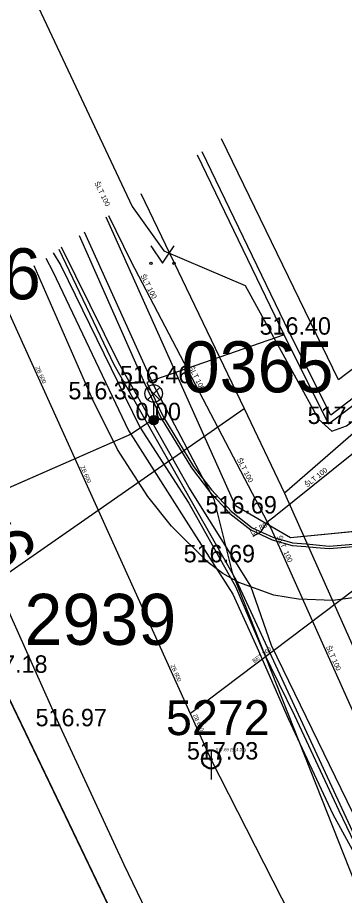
# Model space of a CAD drawing. Extents: x -668867 to -667827, y -1131943 to -1131019.
# Drawn here: x -668558.26 to -668544.21, y -1131122.93 to -1131085.18 of the extents above; entities that cross this region are included whole.
import ezdxf

# ---------------------------------------------------------------- set-up
doc = ezdxf.new("R2010")
doc.units = 0
for name, color, linetype in [('G_Bod_tecka', 7, 'Continuous'), ('G_Bod_vyska', 7, 'Continuous'), ('G_Bodove_pole', 7, 'Continuous'), ('G_Objekty_technicke', 7, 'Continuous'), ('G_Plochy_zpevnene', 7, 'Continuous'), ('G_Ploty', 7, 'Continuous'), ('G_Site-kanalizace', 7, 'Continuous'), ('G_Z_ELsilove_podz_kotovane', 7, 'Continuous'), ('G_Z_KANAL_podz_kotovane', 7, 'Continuous'), ('G_Z_KANAL_podz_priblizne', 7, 'Continuous'), ('G_Z_PLYNY_podz_geodeticky', 7, 'Continuous'), ('G_Z_PLYNY_podz_priblizne', 7, 'Continuous'), ('G_Z_SPOJE_podz_kotovane', 7, 'Continuous'), ('G_Z_VODA_podz_kotovane', 7, 'Continuous'), ('G_Zelen-okraj', 7, 'Continuous'), ('G_Zelen-Znacky', 7, 'Continuous'), ('Vrstva 1', 7, 'Continuous'), ('Vrstva 10', 7, 'Continuous'), ('Vrstva 17', 7, 'Continuous'), ('Vrstva 2', 7, 'Continuous'), ('Vrstva 25', 7, 'Continuous'), ('Vrstva 27', 7, 'Continuous'), ('Vrstva 3', 7, 'Continuous'), ('Vrstva 4', 7, 'Continuous'), ('Vrstva 6', 7, 'Continuous'), ('Vrstva 62', 7, 'Continuous'), ('Vrstva 7', 7, 'Continuous'), ('Vrstva 8', 7, 'Continuous')]:
    doc.layers.add(name, color=color, linetype=linetype)

msp = doc.modelspace()

# ---------------------------------------------------------------- linework, layer by layer
at = {"layer": 'G_Bod_tecka'}
for p, q in [((-668546.8, -1131098.82), (-668546.8, -1131098.82)), ((-668552.81, -1131100.91), (-668552.81, -1131100.91)), ((-668555.04, -1131101.6), (-668555.04, -1131101.6)), ((-668552.41, -1131102.5), (-668552.41, -1131102.5)), ((-668544.89, -1131102.66), (-668544.89, -1131102.66)), ((-668549.14, -1131106.51), (-668549.14, -1131106.51)), ((-668550.07, -1131108.61), (-668550.07, -1131108.61)), ((-668556.45, -1131115.66), (-668556.45, -1131115.66)), ((-668549.94, -1131117.09), (-668549.94, -1131117.09))]:
    msp.add_line(p, q, dxfattribs=at)
at = {"layer": 'G_Bodove_pole'}
for radius in [0.412, 0.05]:
    msp.add_circle((-668549.94, -1131117.08), radius, dxfattribs=at)
at = {"layer": 'G_Objekty_technicke'}
for p, q in [((-668552.675, -1131101.085), (-668552.145, -1131101.615)), ((-668552.675, -1131101.615), (-668552.145, -1131101.085)), ((-668552.41, -1131102.5), (-668552.41, -1131101.725))]:
    msp.add_line(p, q, dxfattribs=at)
for centre, radius in [((-668552.41, -1131101.35), 0.375), ((-668552.41, -1131102.5), 0.2), ((-668552.41, -1131102.5), 0.18), ((-668552.41, -1131102.5), 0.16), ((-668552.41, -1131102.5), 0.14), ((-668552.41, -1131102.5), 0.12), ((-668552.41, -1131102.5), 0.1), ((-668552.41, -1131102.5), 0.08), ((-668552.41, -1131102.5), 0.06), ((-668552.41, -1131102.5), 0.04), ((-668552.41, -1131102.5), 0.02)]:
    msp.add_circle(centre, radius, dxfattribs=at)
at = {"layer": 'G_Plochy_zpevnene'}
for points in [[(-668555.614, -1131094.549), (-668552.81, -1131100.91), (-668552.09, -1131102.41), (-668550.79, -1131104.55), (-668550.01, -1131105.56), (-668549.14, -1131106.51), (-668548.23, -1131107.21), (-668547.32, -1131107.64), (-668546.46, -1131107.88), (-668545.87, -1131107.93)], [(-668539.29, -1131108.57), (-668540.5, -1131109.23), (-668541.66, -1131109.69), (-668542.75, -1131109.99), (-668544.71, -1131110.25), (-668546.18, -1131110.2), (-668547.25, -1131110.02), (-668548.75, -1131109.48), (-668549.44, -1131109.09), (-668550.07, -1131108.61), (-668551.64, -1131107.05), (-668552.66, -1131105.78), (-668553.97, -1131103.76), (-668555.04, -1131101.6), (-668557.551, -1131095.863)], [(-668545.42, -1131107.97), (-668544.86, -1131108.02), (-668543.64, -1131107.92), (-668541.89, -1131107.44), (-668541.1, -1131107.07), (-668540.39, -1131106.62), (-668538.52, -1131105.25), (-668536.64, -1131103.87)], [(-668561.33, -1131104.57), (-668558.95, -1131110.03), (-668556.86, -1131114.73)], [(-668545.87, -1131107.93), (-668545.42, -1131107.97)], [(-668556.86, -1131114.73), (-668556.45, -1131115.66), (-668553.7, -1131121.6), (-668550.85, -1131127.49), (-668546.94, -1131135.61), (-668544.9, -1131139.62), (-668542.72, -1131143.56), (-668539.41, -1131149.26), (-668536.1, -1131154.95)]]:
    msp.add_lwpolyline(points, dxfattribs=at)
at = {"layer": 'G_Ploty'}
for p, q in [((-668546.8, -1131098.82), (-668550.532, -1131091.101)), ((-668546.58, -1131098.71), (-668550.324, -1131090.959)), ((-668529.979, -1131090.988), (-668544.8, -1131102.28)), ((-668544.8, -1131102.28), (-668546.58, -1131098.71)), ((-668544.89, -1131102.66), (-668546.8, -1131098.82)), ((-668544.89, -1131102.66), (-668542.85, -1131101.1))]:
    msp.add_line(p, q, dxfattribs=at)
at = {"layer": 'G_Site-kanalizace'}
msp.add_line((-668549.94, -1131116.705), (-668549.94, -1131117.955), dxfattribs=at)
msp.add_circle((-668549.94, -1131117.08), 0.375, dxfattribs=at)
at = {"layer": 'G_Z_ELsilove_podz_kotovane'}
for points in [[(-668526.115, -1131093.407), (-668536.63, -1131101.38), (-668536.98, -1131103.17), (-668542.54, -1131107.17), (-668546.53, -1131107.55), (-668548.89, -1131106.18), (-668554.451, -1131093.76)], [(-668555.398, -1131094.402), (-668552.424, -1131100.994), (-668549.819, -1131105.896), (-668549.036, -1131109.044), (-668543.513, -1131123.011), (-668538.77, -1131133.046), (-668533.966, -1131143.005), (-668533.886, -1131143.112), (-668529.079, -1131151.328), (-668522.184, -1131161.928), (-668516.261, -1131170.305), (-668508.028, -1131181.583), (-668500.536, -1131191.955), (-668492.492, -1131202.47), (-668484.337, -1131212.694), (-668478.332, -1131220.418)], [(-668556.726, -1131095.303), (-668556.406, -1131095.839), (-668552.998, -1131102.792), (-668550.898, -1131106.069), (-668548.891, -1131109.648), (-668547.699, -1131112.441), (-668546.351, -1131115.199), (-668544.45, -1131119.279), (-668543.13, -1131122.027), (-668541.308, -1131124.675)], [(-668556.493, -1131095.145), (-668554.122, -1131100.103), (-668548.87, -1131109.379), (-668543.078, -1131121.886), (-668542.515, -1131122.204), (-668542.111, -1131122.06), (-668541.748, -1131121.675), (-668541.426, -1131121.211), (-668539.241, -1131119.33), (-668532.251, -1131112.431), (-668526.488, -1131107.968), (-668516.979, -1131100.808), (-668515.738, -1131099.903)], [(-668515.975, -1131099.754), (-668517.114, -1131100.593), (-668526.709, -1131107.733), (-668532.411, -1131112.155), (-668539.445, -1131119.017), (-668541.629, -1131121.118), (-668541.933, -1131121.431), (-668542.228, -1131121.662), (-668542.512, -1131121.611), (-668542.843, -1131121.448), (-668547.35, -1131112.191), (-668548.24, -1131109.636), (-668550.9, -1131105.378), (-668553.911, -1131100.051), (-668556.371, -1131095.062)], [(-668557.051, -1131095.523), (-668556.743, -1131096.102), (-668553.492, -1131102.946), (-668550.913, -1131106.998), (-668549.012, -1131109.978), (-668547.955, -1131112.287), (-668546.633, -1131115.322), (-668544.714, -1131119.434), (-668543.785, -1131121.123), (-668541.478, -1131124.83), (-668538.089, -1131130.556), (-668535.412, -1131135.334), (-668534.618, -1131136.572), (-668534.429, -1131136.881), (-668533.477, -1131138.214), (-668529.506, -1131144.107), (-668526.905, -1131148.152), (-668522.931, -1131152.878), (-668519.382, -1131156.103)], [(-668552.41, -1131102.5), (-668552.51, -1131102.51), (-668553.38, -1131103.1), (-668561.16, -1131106.51)], [(-668561.16, -1131106.51), (-668559.79, -1131110.01), (-668559.58, -1131111.71), (-668559.44, -1131112.79), (-668559.17, -1131113.36), (-668546.16, -1131140.45), (-668534.4, -1131161.49), (-668517.32, -1131185.65), (-668499.12, -1131209.6), (-668480.38, -1131233.31), (-668462.37, -1131256.28), (-668449.58, -1131276.8), (-668449.84, -1131279.37), (-668430.91, -1131303.38), (-668427.62, -1131304.54), (-668413.74, -1131320.95)]]:
    msp.add_lwpolyline(points, dxfattribs=at)
at = {"layer": 'G_Z_KANAL_podz_kotovane'}
for p, q in [((-668549.94, -1131117.09), (-668559.087, -1131096.905)), ((-668531.15, -1131153.93), (-668549.94, -1131117.09))]:
    msp.add_line(p, q, dxfattribs=at)
at = {"layer": 'G_Z_KANAL_podz_priblizne'}
msp.add_lwpolyline([(-668523.912, -1131094.786), (-668550.83, -1131115.11)], dxfattribs=at)
at = {"layer": 'G_Z_PLYNY_podz_geodeticky'}
msp.add_lwpolyline([(-668552.955, -1131092.745), (-668548.52, -1131102), (-668546.79, -1131105.63)], dxfattribs=at)
at = {"layer": 'G_Z_PLYNY_podz_priblizne'}
for points in [[(-668539.12, -1131098.97), (-668546.79, -1131105.63)], [(-668561.1, -1131110.91), (-668560.14, -1131110.15), (-668559.68, -1131109.76), (-668548.52, -1131102)], [(-668546.79, -1131105.63), (-668529.76, -1131143.74)]]:
    msp.add_lwpolyline(points, dxfattribs=at)
at = {"layer": 'G_Z_SPOJE_podz_kotovane'}
msp.add_lwpolyline([(-668579.39, -1131038.72), (-668577.88, -1131039.49), (-668576.69, -1131040.76), (-668575.65, -1131042.87), (-668574.81, -1131045.63), (-668573.68, -1131047.21), (-668572.76, -1131050.24), (-668569.53, -1131057.78), (-668558.64, -1131082.03), (-668553.34, -1131093.31), (-668551.98, -1131095.21), (-668548.48, -1131096.71), (-668546.28, -1131100.71), (-668545.33, -1131102.45), (-668544.75, -1131102.97), (-668544.12, -1131102.74), (-668543.08, -1131101.93), (-668542.34, -1131101.35), (-668541.74, -1131101.57), (-668541.1, -1131102.41), (-668539.63, -1131104.24), (-668539.37, -1131104.77)], dxfattribs=at)
at = {"layer": 'G_Z_VODA_podz_kotovane'}
for points in [[(-668547.53, -1131106.87), (-668547.24, -1131106.65), (-668528.724, -1131091.774)], [(-668554.356, -1131093.695), (-668553.39, -1131095.66), (-668547.53, -1131106.87), (-668547.37, -1131107.14), (-668535.16, -1131134.42), (-668524.68, -1131156.69), (-668524.68, -1131156.69), (-668514.04, -1131173.18), (-668502.91, -1131189.19), (-668501.17, -1131191.76), (-668498.15, -1131195.68), (-668493.12, -1131202.03), (-668493.02, -1131202.16), (-668492.31, -1131203.14)], [(-668547.53, -1131106.87), (-668547.83, -1131107.33), (-668548.15, -1131107.49)]]:
    msp.add_lwpolyline(points, dxfattribs=at)
at = {"layer": 'G_Zelen-okraj'}
for p, q in [((-668544.46, -1131100.76), (-668549.499, -1131090.4)), ((-668530.903, -1131090.41), (-668544.46, -1131100.76)), ((-668546.8, -1131098.82), (-668552.71, -1131100.87))]:
    msp.add_line(p, q, dxfattribs=at)
for points in [[(-668552.71, -1131100.87), (-668551.99, -1131102.36), (-668550.7, -1131104.49), (-668549.93, -1131105.49), (-668549.06, -1131106.43), (-668548.18, -1131107.12), (-668547.29, -1131107.53), (-668546.44, -1131107.77), (-668545.86, -1131107.82), (-668545.42, -1131107.86)], [(-668545.42, -1131107.86), (-668544.86, -1131107.92), (-668543.66, -1131107.81), (-668541.93, -1131107.34), (-668541.16, -1131106.98), (-668540.44, -1131106.53)]]:
    msp.add_lwpolyline(points, dxfattribs=at)
at = {"layer": 'G_Zelen-Znacky'}
for p, q in [((-668552.53, -1131095), (-668552.03, -1131095.75)), ((-668552.03, -1131095.75), (-668551.53, -1131095))]:
    msp.add_line(p, q, dxfattribs=at)
for centre in [(-668552.53, -1131095.75), (-668551.53, -1131095.75)]:
    msp.add_circle(centre, 0.05, dxfattribs=at)
at = {"layer": 'Vrstva 1'}
msp.add_line((-668552.41, -1131102.5), (-668552.41, -1131102.5), dxfattribs=at)
at = {"layer": 'Vrstva 10'}
for p, q in [((-668549.938, -1131117.085), (-668559.083, -1131096.902)), ((-668531.151, -1131153.926), (-668549.938, -1131117.085))]:
    msp.add_line(p, q, dxfattribs=at)
at = {"layer": 'Vrstva 17'}
for p, q in [((-668548.89, -1131106.18), (-668554.451, -1131093.76)), ((-668546.53, -1131107.55), (-668548.89, -1131106.18)), ((-668542.54, -1131107.17), (-668546.53, -1131107.55)), ((-668559.17, -1131113.36), (-668546.16, -1131140.45))]:
    msp.add_line(p, q, dxfattribs=at)
msp.add_lwpolyline([(-668523.912, -1131094.786), (-668550.83, -1131115.11), (-668550.832, -1131115.112)], dxfattribs=at)
at = {"layer": 'Vrstva 25'}
msp.add_lwpolyline([(-668547.53, -1131106.872), (-668547.83, -1131107.327), (-668548.148, -1131107.492)], dxfattribs=at)
at = {"layer": 'Vrstva 27'}
for points in [[(-668547.53, -1131106.872), (-668547.238, -1131106.651), (-668528.724, -1131091.774)], [(-668554.359, -1131093.697), (-668553.394, -1131095.659), (-668547.53, -1131106.872), (-668547.372, -1131107.14), (-668535.158, -1131134.419), (-668524.68, -1131156.688), (-668524.679, -1131156.689), (-668514.04, -1131173.182), (-668502.909, -1131189.194), (-668501.166, -1131191.758), (-668498.148, -1131195.679), (-668493.124, -1131202.026), (-668493.025, -1131202.162), (-668492.315, -1131203.139)]]:
    msp.add_lwpolyline(points, dxfattribs=at)
at = {"layer": 'Vrstva 6'}
for p, q in [((-668547.238, -1131106.651), (-668547.238, -1131106.651)), ((-668547.83, -1131107.327), (-668547.83, -1131107.327)), ((-668547.372, -1131107.14), (-668547.372, -1131107.14))]:
    msp.add_line(p, q, dxfattribs=at)
at = {"layer": 'Vrstva 62'}
for p, q in [((-668552.51, -1131102.51), (-668553.38, -1131103.1)), ((-668552.41, -1131102.5), (-668552.51, -1131102.51)), ((-668553.38, -1131103.1), (-668561.16, -1131106.51))]:
    msp.add_line(p, q, dxfattribs=at)
at = {"layer": 'Vrstva 7'}
msp.add_line((-668548.148, -1131107.492), (-668548.148, -1131107.492), dxfattribs=at)
at = {"layer": 'Vrstva 8'}
msp.add_line((-668549.938, -1131117.085), (-668549.938, -1131117.085), dxfattribs=at)

# ---------------------------------------------------------------- texts
at = {"layer": 'G_Bod_vyska'}
for s, p in [('516.40', (-668547.858, -1131098.82)), ('516.46', (-668553.86, -1131100.91)), ('516.35', (-668556.076, -1131101.6)), ('0.00', (-668553.19, -1131102.5)), ('517.10', (-668545.792, -1131102.66)), ('516.69', (-668550.182, -1131106.51)), ('516.69', (-668551.122, -1131108.61)), ('517.18', (-668560.041, -1131113.36)), ('516.97', (-668557.488, -1131115.66)), ('517.03', (-668550.981, -1131117.09))]:
    msp.add_text(s, height=0.75, dxfattribs=at).set_placement(p)
at = {"layer": 'G_Bodove_pole'}
msp.add_text('5272', height=1.5, dxfattribs=at).set_placement((-668551.883, -1131116.04))
at = {"layer": 'Vrstva 2'}
msp.add_text('517.89 (514.36)', height=0.13163, dxfattribs=at).set_placement((-668549.733, -1131116.732))
at = {"layer": 'Vrstva 3'}
for s, height, rotation, p in [('CYKY  - 5x6', 2.19389, 294.1351, (-668565.966, -1131094.491)), ('ZB 600', 0.1755, 294.3701, (-668557.499, -1131100.228)), ('ZB 600', 0.1755, 294.3129, (-668555.563, -1131104.502)), ('BET 300', 0.1755, 37.0474, (-668548.085, -1131112.95)), ('ZB 600', 0.1755, 294.3869, (-668551.691, -1131113.047)), ('ZB 600', 0.1755, 294.2962, (-668550.723, -1131115.183))]:
    msp.add_text(s, height=height, rotation=rotation, dxfattribs=at).set_placement(p)
at = {"layer": 'Vrstva 4'}
for s, rotation, p in [('ŠLT 100', 296.2058, (-668554.969, -1131092.297)), ('ŠLT 100', 297.6236, (-668552.984, -1131096.289)), ('ŠLT 100', 297.6557, (-668550.912, -1131100.239)), ('ŠLT 100', 297.6557, (-668548.84, -1131104.189)), ('ŠLT 100', 38.7404, (-668545.808, -1131105.398)), ('LT 80', 28.8285, (-668548.191, -1131107.448)), ('ŠLT  100', 294.1997, (-668547.129, -1131107.514)), ('ŠLT 100', 294.146, (-668545.009, -1131112.247))]:
    msp.add_text(s, height=0.2194, rotation=rotation, dxfattribs=at).set_placement(p)
for s, p in [('0366', (-668563.787, -1131097.298)), ('0365', (-668551.207, -1131101.299)), ('2939', (-668557.967, -1131112.158))]:
    msp.add_text(s, height=2.1939, dxfattribs=at).set_placement(p)

doc.saveas('drawing.dxf')
